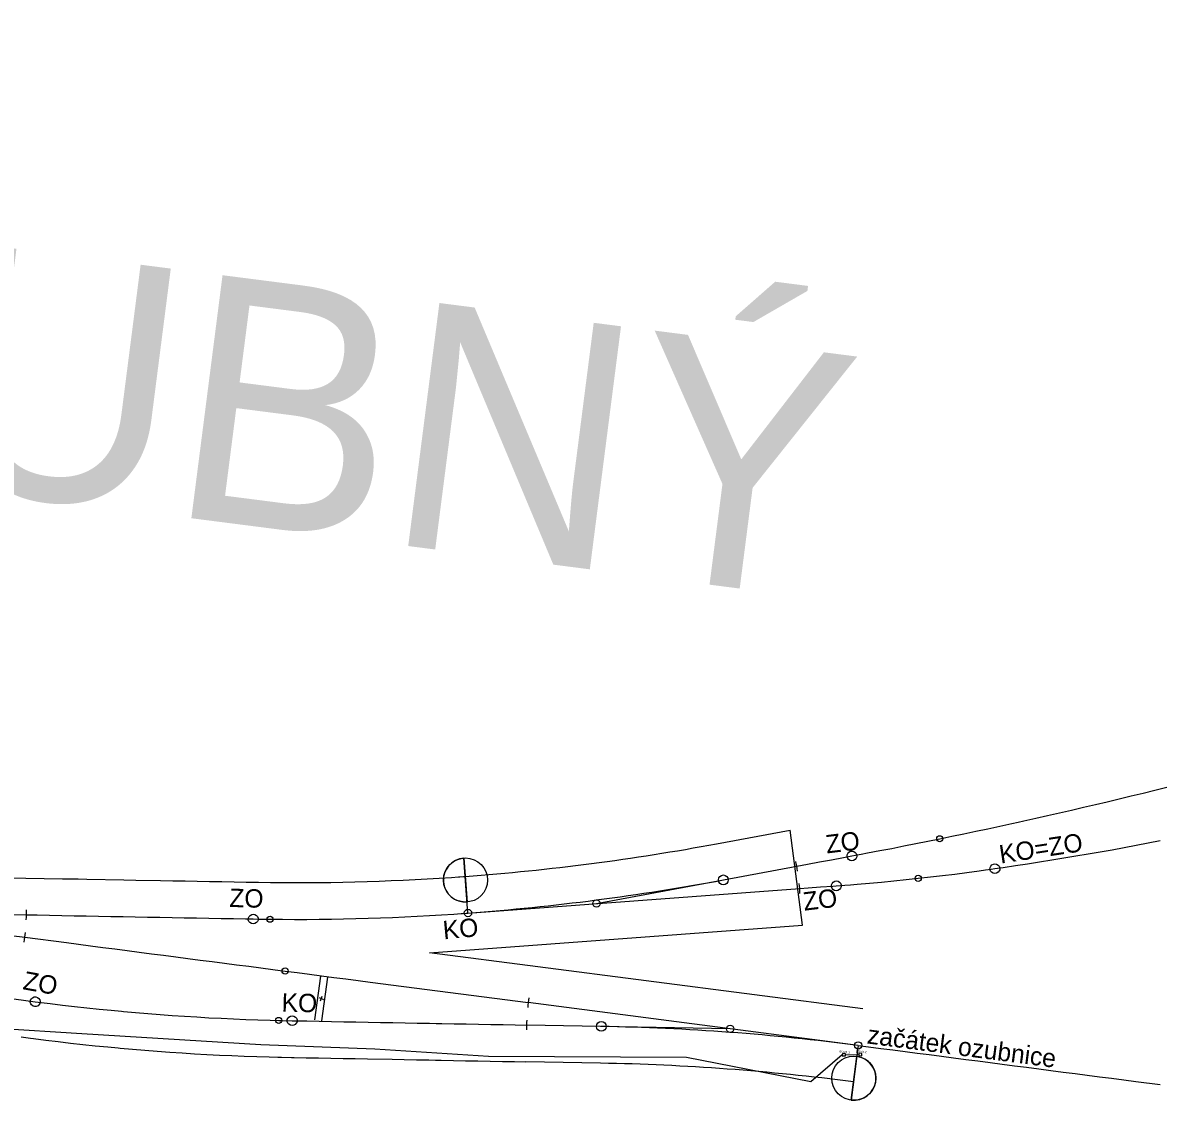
# Model space of a CAD drawing. Extents: x -669661 to -669105, y -977202 to -977030.
# Drawn here: x -669172.695 to -669168.055, y -977098.531 to -977094.133 of the extents above; entities that cross this region are included whole.
import ezdxf

# ---------------------------------------------------------------- set-up
doc = ezdxf.new("R2010")
doc.units = 0
doc.layers.add('KOL_námezníky', color=7, linetype='Continuous')
doc.layers.add('Schéma', color=7, linetype='Continuous')

# ---------------------------------------------------------------- blocks, each defined once
blk = doc.blocks.new('Z3.50')
at = {"layer": 'KOL_námezníky'}
for p, q in [((-27.7, 181.3), (-26.5, -174.8)), ((33.2, -174.7), (31.9, 181.4))]:
    blk.add_line(p, q, dxfattribs=at)

msp = doc.modelspace()

# ---------------------------------------------------------------- linework, layer by layer
at = {"layer": 'Schéma'}
for p, q in [((-669168.1733, -977097.2885), (-669168.1247, -977097.2766)), ((-669168.1247, -977097.2766), (-669168.0762, -977097.2646)), ((-669168.0762, -977097.2646), (-669168.0277, -977097.2524)), ((-669168.3678, -977097.3349), (-669168.3192, -977097.3235)), ((-669168.3192, -977097.3235), (-669168.2705, -977097.3119)), ((-669168.2705, -977097.3119), (-669168.2219, -977097.3002)), ((-669168.2219, -977097.3002), (-669168.1733, -977097.2885)), ((-669168.5628, -977097.3795), (-669168.514, -977097.3685)), ((-669168.514, -977097.3685), (-669168.4653, -977097.3574)), ((-669168.4653, -977097.3574), (-669168.4165, -977097.3462)), ((-669168.4165, -977097.3462), (-669168.3678, -977097.3349)), ((-669168.7582, -977097.4223), (-669168.7093, -977097.4118)), ((-669168.7093, -977097.4118), (-669168.6604, -977097.4011)), ((-669168.6604, -977097.4011), (-669168.6347, -977097.3955)), ((-669168.6347, -977097.3955), (-669168.6116, -977097.3904)), ((-669168.6116, -977097.3904), (-669168.5628, -977097.3795)), ((-669169.8644, -977097.4837), (-669169.5649, -977097.4278)), ((-669169.5145, -977097.816), (-669169.5649, -977097.4278)), ((-669169.0029, -977097.4732), (-669168.9539, -977097.4632)), ((-669168.9539, -977097.4632), (-669168.9049, -977097.4532)), ((-669168.9049, -977097.4532), (-669168.856, -977097.443)), ((-669168.856, -977097.443), (-669168.8071, -977097.4327)), ((-669168.8071, -977097.4327), (-669168.7582, -977097.4223)), ((-669169.2483, -977097.5212), (-669169.1992, -977097.5118)), ((-669169.1992, -977097.5118), (-669169.1501, -977097.5024)), ((-669169.1501, -977097.5024), (-669169.101, -977097.4927)), ((-669169.101, -977097.4927), (-669169.0519, -977097.483)), ((-669169.0519, -977097.483), (-669169.0029, -977097.4732)), ((-669168.3001, -977097.5166), (-669168.2508, -977097.5079)), ((-669168.2508, -977097.5079), (-669168.2016, -977097.4989)), ((-669168.2016, -977097.4989), (-669168.1525, -977097.4898)), ((-669168.1525, -977097.4898), (-669168.1034, -977097.4805)), ((-669168.1034, -977097.4805), (-669168.0543, -977097.471)), ((-669170.8788, -977097.7664), (-669170.8954, -977097.542)), ((-669169.494, -977097.5672), (-669169.4449, -977097.558)), ((-669169.4449, -977097.558), (-669169.3957, -977097.5488)), ((-669169.3957, -977097.5488), (-669169.3465, -977097.5397)), ((-669169.3465, -977097.5397), (-669169.3122, -977097.5332)), ((-669169.3122, -977097.5332), (-669169.2974, -977097.5305)), ((-669169.2974, -977097.5305), (-669169.2742, -977097.5261)), ((-669169.2742, -977097.5261), (-669169.2483, -977097.5212)), ((-669168.5961, -977097.5654), (-669168.5467, -977097.5577)), ((-669168.5467, -977097.5577), (-669168.4973, -977097.5499)), ((-669168.4973, -977097.5499), (-669168.4479, -977097.5418)), ((-669168.4479, -977097.5418), (-669168.3986, -977097.5336)), ((-669168.3986, -977097.5336), (-669168.3493, -977097.5252)), ((-669168.3493, -977097.5252), (-669168.3001, -977097.5166)), ((-669170.3541, -977097.7276), (-669169.5374, -977097.5753)), ((-669169.5374, -977097.5753), (-669169.494, -977097.5672)), ((-669168.8931, -977097.6072), (-669168.8435, -977097.6008)), ((-669168.8435, -977097.6008), (-669168.794, -977097.5942)), ((-669168.794, -977097.5942), (-669168.7673, -977097.5905)), ((-669168.7673, -977097.5905), (-669168.7445, -977097.5873)), ((-669168.7445, -977097.5873), (-669168.7292, -977097.5852)), ((-669168.7292, -977097.5852), (-669168.695, -977097.5802)), ((-669168.695, -977097.5802), (-669168.6455, -977097.5729)), ((-669168.6455, -977097.5729), (-669168.5961, -977097.5654)), ((-669169.3761, -977097.6553), (-669169.3408, -977097.6527)), ((-669169.3408, -977097.6527), (-669169.3178, -977097.6508)), ((-669169.3178, -977097.6508), (-669169.291, -977097.6487)), ((-669169.291, -977097.6487), (-669169.2411, -977097.6444)), ((-669169.2411, -977097.6444), (-669169.1913, -977097.6399)), ((-669169.1913, -977097.6399), (-669169.1416, -977097.6351)), ((-669169.1416, -977097.6351), (-669169.0918, -977097.63)), ((-669169.0918, -977097.63), (-669169.0421, -977097.6247)), ((-669169.0421, -977097.6247), (-669168.9924, -977097.6191)), ((-669168.9924, -977097.6191), (-669168.9428, -977097.6133)), ((-669168.9428, -977097.6133), (-669168.8931, -977097.6072)), ((-669174.0323, -977097.6905), (-669172.6867, -977097.8652)), ((-669170.8788, -977097.7664), (-669169.5256, -977097.6664)), ((-669169.5256, -977097.6664), (-669169.4904, -977097.6638)), ((-669169.4904, -977097.6638), (-669169.4405, -977097.6601)), ((-669169.4405, -977097.6601), (-669169.3907, -977097.6564)), ((-669169.3907, -977097.6564), (-669169.3761, -977097.6553)), ((-669173.5106, -977097.7582), (-669172.6799, -977097.7736)), ((-669172.6799, -977097.7736), (-669172.6358, -977097.7744)), ((-669172.6358, -977097.7744), (-669172.5858, -977097.7753)), ((-669172.5858, -977097.7753), (-669172.5358, -977097.7762)), ((-669172.5358, -977097.7762), (-669172.4858, -977097.7772)), ((-669172.4858, -977097.7772), (-669172.4713, -977097.7774)), ((-669172.4713, -977097.7774), (-669172.4358, -977097.7781)), ((-669172.4358, -977097.7781), (-669172.3858, -977097.779)), ((-669172.3858, -977097.779), (-669172.3358, -977097.7799)), ((-669172.3358, -977097.7799), (-669172.2859, -977097.7809)), ((-669172.2859, -977097.7809), (-669172.2359, -977097.7818)), ((-669172.2359, -977097.7818), (-669172.1859, -977097.7827)), ((-669172.1859, -977097.7827), (-669172.1359, -977097.7836)), ((-669172.1359, -977097.7836), (-669172.0859, -977097.7846)), ((-669172.0859, -977097.7846), (-669172.0359, -977097.7855)), ((-669172.0359, -977097.7855), (-669171.9859, -977097.7864)), ((-669171.9859, -977097.7864), (-669171.9359, -977097.7873)), ((-669171.9359, -977097.7873), (-669171.8859, -977097.7882)), ((-669171.8859, -977097.7882), (-669171.8359, -977097.7892)), ((-669171.8359, -977097.7892), (-669171.7859, -977097.7901)), ((-669171.7859, -977097.7901), (-669171.7547, -977097.7907)), ((-669171.7547, -977097.7907), (-669171.7359, -977097.791)), ((-669171.7359, -977097.791), (-669171.686, -977097.7917)), ((-669171.686, -977097.7917), (-669171.636, -977097.7921)), ((-669171.536, -977097.7922), (-669171.486, -977097.7918)), ((-669171.486, -977097.7918), (-669171.436, -977097.7912)), ((-669171.436, -977097.7912), (-669171.386, -977097.7903)), ((-669171.386, -977097.7903), (-669171.336, -977097.7892)), ((-669171.336, -977097.7892), (-669171.286, -977097.7878)), ((-669171.286, -977097.7878), (-669171.236, -977097.7861)), ((-669171.236, -977097.7861), (-669171.1861, -977097.7842)), ((-669171.1861, -977097.7842), (-669171.1361, -977097.782)), ((-669171.1361, -977097.782), (-669171.0862, -977097.7795)), ((-669171.0862, -977097.7795), (-669171.0362, -977097.7768)), ((-669171.0362, -977097.7768), (-669170.9863, -977097.7738)), ((-669170.9863, -977097.7738), (-669170.9364, -977097.7705)), ((-669170.9364, -977097.7705), (-669170.907, -977097.7685)), ((-669170.907, -977097.7685), (-669170.901, -977097.7681)), ((-669170.901, -977097.7681), (-669170.8866, -977097.767)), ((-669170.8866, -977097.767), (-669170.8788, -977097.7664)), ((-669171.636, -977097.7921), (-669171.586, -977097.7923)), ((-669171.586, -977097.7923), (-669171.536, -977097.7922)), ((-669171.0352, -977097.9284), (-669169.5145, -977097.816)), ((-669172.6867, -977097.8652), (-669172.5172, -977097.8872)), ((-669172.5172, -977097.8872), (-669172.4676, -977097.8937)), ((-669172.4676, -977097.8937), (-669172.418, -977097.9001)), ((-669172.418, -977097.9001), (-669172.3684, -977097.9065)), ((-669172.3684, -977097.9065), (-669172.3188, -977097.913)), ((-669172.3188, -977097.913), (-669172.2692, -977097.9194)), ((-669172.2692, -977097.9194), (-669172.2197, -977097.9259)), ((-669172.2197, -977097.9259), (-669172.1701, -977097.9323)), ((-669169.2679, -977098.1579), (-669171.0352, -977097.9284)), ((-669172.1701, -977097.9323), (-669172.1205, -977097.9387)), ((-669172.1205, -977097.9387), (-669172.0709, -977097.9452)), ((-669172.0709, -977097.9452), (-669172.0213, -977097.9516)), ((-669172.0213, -977097.9516), (-669171.9717, -977097.9581)), ((-669171.9717, -977097.9581), (-669171.9222, -977097.9645)), ((-669171.9222, -977097.9645), (-669171.8726, -977097.9709)), ((-669171.8726, -977097.9709), (-669171.823, -977097.9774)), ((-669171.823, -977097.9774), (-669171.7734, -977097.9838)), ((-669171.7734, -977097.9838), (-669171.7238, -977097.9902)), ((-669171.7238, -977097.9902), (-669171.6742, -977097.9967)), ((-669171.6742, -977097.9967), (-669171.6246, -977098.0031)), ((-669171.6246, -977098.0031), (-669171.5751, -977098.0096)), ((-669171.5751, -977098.0096), (-669171.5255, -977098.016)), ((-669171.5255, -977098.016), (-669171.4759, -977098.0224)), ((-669171.4759, -977098.0224), (-669171.4263, -977098.0289)), ((-669171.4263, -977098.0289), (-669171.3767, -977098.0353)), ((-669171.3767, -977098.0353), (-669171.3271, -977098.0418)), ((-669171.3271, -977098.0418), (-669171.2776, -977098.0482)), ((-669171.2776, -977098.0482), (-669170.6328, -977098.1319)), ((-669171.4864, -977098.1118), (-669171.4678, -977098.1193)), ((-669171.4809, -977098.1249), (-669171.4735, -977098.1062)), ((-669172.7314, -977098.1171), (-669172.6819, -977098.1235)), ((-669172.6819, -977098.1235), (-669172.644, -977098.1284)), ((-669172.644, -977098.1284), (-669172.6323, -977098.1299)), ((-669172.6323, -977098.1299), (-669172.5827, -977098.1362)), ((-669172.5827, -977098.1362), (-669172.533, -977098.1422)), ((-669172.533, -977098.1422), (-669172.4833, -977098.1479)), ((-669172.4833, -977098.1479), (-669172.4336, -977098.1533)), ((-669172.4336, -977098.1533), (-669172.3839, -977098.1585)), ((-669172.3839, -977098.1585), (-669172.3342, -977098.1635)), ((-669169.2872, -977098.3066), (-669170.6328, -977098.1319)), ((-669172.3342, -977098.1635), (-669172.2923, -977098.1674)), ((-669172.2923, -977098.1674), (-669172.2844, -977098.1682)), ((-669172.2844, -977098.1682), (-669172.2346, -977098.1726)), ((-669172.2346, -977098.1726), (-669172.1848, -977098.1767)), ((-669172.1848, -977098.1767), (-669172.1349, -977098.1806)), ((-669172.1349, -977098.1806), (-669172.085, -977098.1842)), ((-669172.085, -977098.1842), (-669172.0351, -977098.1876)), ((-669172.0351, -977098.1876), (-669171.9852, -977098.1907)), ((-669171.9852, -977098.1907), (-669171.9353, -977098.1935)), ((-669171.9353, -977098.1935), (-669171.8854, -977098.1961)), ((-669171.8854, -977098.1961), (-669171.8354, -977098.1984)), ((-669171.8354, -977098.1984), (-669171.7855, -977098.2005)), ((-669171.7855, -977098.2005), (-669171.7355, -977098.2023)), ((-669171.7355, -977098.2023), (-669171.6855, -977098.2038)), ((-669171.6855, -977098.2038), (-669171.651, -977098.2047)), ((-669171.651, -977098.2047), (-669171.6356, -977098.2051)), ((-669171.6356, -977098.2051), (-669171.5961, -977098.2059)), ((-669171.5961, -977098.2059), (-669171.5856, -977098.2061)), ((-669171.5856, -977098.2061), (-669171.5356, -977098.207)), ((-669171.5356, -977098.207), (-669171.4856, -977098.2079)), ((-669171.4856, -977098.2079), (-669171.4356, -977098.2088)), ((-669171.4356, -977098.2088), (-669171.3856, -977098.2098)), ((-669172.4538, -977098.259), (-669172.8186, -977098.2366)), ((-669171.3856, -977098.2098), (-669171.3356, -977098.2107)), ((-669171.3356, -977098.2107), (-669171.2856, -977098.2116)), ((-669171.2856, -977098.2116), (-669171.2356, -977098.2125)), ((-669171.2356, -977098.2125), (-669171.1856, -977098.2135)), ((-669171.1856, -977098.2135), (-669171.1356, -977098.2144)), ((-669171.1356, -977098.2144), (-669171.0857, -977098.2153)), ((-669171.0857, -977098.2153), (-669171.0357, -977098.2162)), ((-669171.0357, -977098.2162), (-669171.0086, -977098.2167)), ((-669171.0086, -977098.2167), (-669170.9857, -977098.2172)), ((-669170.9857, -977098.2172), (-669170.9357, -977098.2181)), ((-669170.9357, -977098.2181), (-669170.8857, -977098.219)), ((-669170.8857, -977098.219), (-669170.8357, -977098.2199)), ((-669170.8357, -977098.2199), (-669170.7857, -977098.2208)), ((-669170.7857, -977098.2208), (-669170.7357, -977098.2218)), ((-669170.7357, -977098.2218), (-669170.6857, -977098.2227)), ((-669170.6857, -977098.2227), (-669170.6396, -977098.2235)), ((-669169.809, -977098.2389), (-669170.6396, -977098.2235)), ((-669171.7241, -977098.3042), (-669172.4538, -977098.259)), ((-669171.259, -977098.3225), (-669171.7241, -977098.3042)), ((-669170.7944, -977098.3526), (-669171.259, -977098.3225)), ((-669169.3525, -977098.3452), (-669169.4804, -977098.4556)), ((-669169.3513, -977098.3398), (-669169.3518, -977098.3489)), ((-669169.3518, -977098.3489), (-669169.3393, -977098.3495)), ((-669169.3388, -977098.3404), (-669169.3513, -977098.3398)), ((-669169.3393, -977098.3495), (-669169.3388, -977098.3404)), ((-669169.339, -977098.345), (-669169.2844, -977098.3434)), ((-669169.2872, -977098.3066), (-669169.3161, -977098.5298)), ((-669169.2842, -977098.3388), (-669169.2846, -977098.348)), ((-669169.2846, -977098.348), (-669169.2721, -977098.3486)), ((-669169.2716, -977098.3395), (-669169.2842, -977098.3388)), ((-669169.2721, -977098.3486), (-669169.2716, -977098.3395)), ((-669169.9874, -977098.3559), (-669170.7944, -977098.3526)), ((-669170.3378, -977098.3791), (-669170.6423, -977098.3735)), ((-669169.4804, -977098.4556), (-669169.9874, -977098.3559))]:
    msp.add_line(p, q, dxfattribs=at)
for points in [[(-669169.3126, -977097.5532), (-669169.3192, -977097.5518), (-669169.3258, -977097.5477), (-669169.3297, -977097.5436), (-669169.3323, -977097.5369), (-669169.3321, -977097.5289), (-669169.3294, -977097.5236), (-669169.3253, -977097.5183), (-669169.3185, -977097.5145), (-669169.3118, -977097.5133), (-669169.3052, -977097.5147), (-669169.2986, -977097.5188), (-669169.2947, -977097.5229), (-669169.2921, -977097.5296), (-669169.2923, -977097.5376), (-669169.295, -977097.5429), (-669169.2991, -977097.5482), (-669169.3059, -977097.552), (-669169.3126, -977097.5532)], [(-669170.8954, -977097.542), (-669170.8821, -977097.7216), (-669170.8821, -977097.7216)], [(-669168.7295, -977097.6052), (-669168.7362, -977097.6037), (-669168.7428, -977097.5996), (-669168.7467, -977097.5955), (-669168.7492, -977097.5888), (-669168.7491, -977097.5808), (-669168.7463, -977097.5755), (-669168.7422, -977097.5702), (-669168.7355, -977097.5664), (-669168.7288, -977097.5652), (-669168.7222, -977097.5666), (-669168.7156, -977097.5707), (-669168.7116, -977097.5748), (-669168.7091, -977097.5815), (-669168.7092, -977097.5895), (-669168.712, -977097.5948), (-669168.7161, -977097.6001), (-669168.7228, -977097.6039), (-669168.7295, -977097.6052)], [(-669172.9817, -977097.618), (-669172.533, -977097.6263), (-669172.483, -977097.6272), (-669172.4686, -977097.6275), (-669172.4331, -977097.6281), (-669172.2831, -977097.6309), (-669172.2331, -977097.6318), (-669172.1331, -977097.6337), (-669172.0831, -977097.6346), (-669172.0331, -977097.6355), (-669171.9831, -977097.6364), (-669171.9331, -977097.6374), (-669171.8832, -977097.6383), (-669171.8332, -977097.6392), (-669171.7832, -977097.6401), (-669171.752, -977097.6407), (-669171.7336, -977097.641), (-669171.6843, -977097.6417), (-669171.6351, -977097.6421), (-669171.5858, -977097.6423), (-669171.5366, -977097.6422), (-669171.4874, -977097.6418), (-669171.4382, -977097.6412), (-669171.389, -977097.6404), (-669171.3398, -977097.6392), (-669171.2906, -977097.6378), (-669171.2414, -977097.6362), (-669171.1923, -977097.6343), (-669171.1431, -977097.6321), (-669171.094, -977097.6297), (-669171.0448, -977097.627), (-669170.9957, -977097.6241), (-669170.9465, -977097.6209), (-669170.9176, -977097.6188), (-669170.9118, -977097.6184), (-669170.8975, -977097.6174), (-669170.8898, -977097.6168)], [(-669169.3765, -977097.6753), (-669169.3831, -977097.6739), (-669169.3897, -977097.6698), (-669169.3937, -977097.6657), (-669169.3962, -977097.659), (-669169.3961, -977097.651), (-669169.3933, -977097.6457), (-669169.3892, -977097.6404), (-669169.3825, -977097.6366), (-669169.3758, -977097.6353), (-669169.3691, -977097.6368), (-669169.3625, -977097.6409), (-669169.3586, -977097.645), (-669169.3561, -977097.6517), (-669169.3562, -977097.6597), (-669169.359, -977097.665), (-669169.3631, -977097.6702), (-669169.3698, -977097.6741), (-669169.3765, -977097.6753)], [(-669171.755, -977097.8107), (-669171.7617, -977097.8092), (-669171.7683, -977097.8051), (-669171.7722, -977097.801), (-669171.7748, -977097.7943), (-669171.7746, -977097.7863), (-669171.7718, -977097.781), (-669171.7677, -977097.7758), (-669171.761, -977097.7719), (-669171.7543, -977097.7707), (-669171.7477, -977097.7721), (-669171.7411, -977097.7763), (-669171.7372, -977097.7803), (-669171.7346, -977097.787), (-669171.7348, -977097.795), (-669171.7375, -977097.8003), (-669171.7416, -977097.8056), (-669171.7484, -977097.8095), (-669171.755, -977097.8107)], [(-669172.6466, -977098.1482), (-669172.653, -977098.1461), (-669172.6591, -977098.1412), (-669172.6625, -977098.1368), (-669172.6643, -977098.1298), (-669172.6633, -977098.1219), (-669172.66, -977098.1169), (-669172.6553, -977098.1121), (-669172.6482, -977098.109), (-669172.6414, -977098.1086), (-669172.635, -977098.1108), (-669172.6289, -977098.1156), (-669172.6254, -977098.1201), (-669172.6236, -977098.127), (-669172.6247, -977098.135), (-669172.628, -977098.1399), (-669172.6327, -977098.1447), (-669172.6398, -977098.1478), (-669172.6466, -977098.1482)], [(-669171.5965, -977098.2259), (-669171.6031, -977098.2244), (-669171.6097, -977098.2203), (-669171.6137, -977098.2162), (-669171.6162, -977098.2095), (-669171.6161, -977098.2015), (-669171.6133, -977098.1962), (-669171.6092, -977098.191), (-669171.6025, -977098.1871), (-669171.5958, -977098.1859), (-669171.5891, -977098.1873), (-669171.5825, -977098.1915), (-669171.5786, -977098.1955), (-669171.5761, -977098.2022), (-669171.5762, -977098.2102), (-669171.579, -977098.2155), (-669171.5831, -977098.2208), (-669171.5898, -977098.2247), (-669171.5965, -977098.2259)], [(-669172.7012, -977098.2722), (-669172.6633, -977098.2772), (-669172.6512, -977098.2787), (-669172.601, -977098.285), (-669172.5506, -977098.2911), (-669172.5001, -977098.2969), (-669172.4496, -977098.3025), (-669172.3991, -977098.3078), (-669172.3486, -977098.3128), (-669172.3062, -977098.3168), (-669172.2979, -977098.3176), (-669172.2474, -977098.322), (-669172.1968, -977098.3262), (-669172.1462, -977098.3302), (-669172.0955, -977098.3339), (-669172.0448, -977098.3373), (-669171.9942, -977098.3404), (-669171.9435, -977098.3433), (-669171.8927, -977098.3459), (-669171.842, -977098.3483), (-669171.7912, -977098.3504), (-669171.7405, -977098.3522), (-669171.6898, -977098.3537), (-669171.6547, -977098.3547), (-669171.6389, -977098.355), (-669171.5991, -977098.3558), (-669171.5883, -977098.356), (-669171.5383, -977098.357), (-669171.4884, -977098.3579), (-669171.4384, -977098.3588), (-669171.3884, -977098.3597), (-669171.3384, -977098.3607), (-669171.2884, -977098.3616), (-669171.1884, -977098.3634), (-669171.1384, -977098.3644), (-669171.0884, -977098.3653), (-669171.0384, -977098.3662), (-669171.0113, -977098.3667), (-669170.9884, -977098.3671), (-669170.9384, -977098.368), (-669170.8885, -977098.369), (-669170.8385, -977098.3699), (-669170.7385, -977098.3717), (-669170.6885, -977098.3727), (-669170.6423, -977098.3735)], [(-669169.2872, -977098.3066), (-669169.2446, -977098.3122), (-669169.195, -977098.3186), (-669169.1455, -977098.325), (-669169.0959, -977098.3315), (-669169.0463, -977098.3379), (-669168.9967, -977098.3444), (-669168.9471, -977098.3508), (-669168.8975, -977098.3572), (-669168.848, -977098.3637), (-669168.7984, -977098.3701), (-669168.7488, -977098.3765), (-669168.6992, -977098.383), (-669168.6496, -977098.3894), (-669168.6, -977098.3959), (-669168.5505, -977098.4023), (-669168.5009, -977098.4087), (-669168.4513, -977098.4152), (-669168.4017, -977098.4216), (-669168.3521, -977098.428), (-669168.3025, -977098.4345), (-669168.253, -977098.4409), (-669168.2034, -977098.4474), (-669168.1538, -977098.4538), (-669168.0546, -977098.4667)], [(-669169.3161, -977098.5298), (-669169.293, -977098.3513), (-669169.293, -977098.3513)]]:
    msp.add_lwpolyline(points, dxfattribs=at)
for centre, radius in [((-669168.9541, -977097.4633), 0.0125), ((-669170.8888, -977097.6318), 0.09), ((-669169.8368, -977097.6311), 0.02), ((-669169.0421, -977097.6247), 0.0125), ((-669170.3541, -977097.7276), 0.015), ((-669171.686, -977097.7917), 0.0125), ((-669170.8788, -977097.7664), 0.015), ((-669171.6246, -977098.0031), 0.0125), ((-669171.651, -977098.2047), 0.0125), ((-669170.335, -977098.2292), 0.02), ((-669169.809, -977098.2389), 0.015), ((-669169.2872, -977098.3066), 0.015), ((-669169.3046, -977098.4405), 0.09)]:
    msp.add_circle(centre, radius, dxfattribs=at)
for centre, radius, start, end in [((-669171.5793, -977088.2923), 9.35, 274.22836, 280.56855), ((-669170.8888, -977097.6318), 0.09, 94.2284, 274.2269), ((-669170.3541, -977097.7276), 0.8308, 9.1892, 11.9479), ((-669171.5793, -977088.2923), 9.5, 274.22836, 280.56839), ((-669170.3541, -977097.7276), 0.8308, 2.849, 5.6077), ((-669173.5106, -977097.7582), 0.8308, 357.5628, 0.3215), ((-669173.5106, -977097.7582), 0.8308, 351.2226, 353.9813), ((-669169.8089, -977098.2389), 0.8308, 171.2226, 173.9813), ((-669169.8089, -977098.2389), 0.8308, 177.5628, 180.3215), ((-669170.5104, -977107.7276), 9.5, 82.60197, 88.942), ((-669170.5104, -977107.7276), 9.35, 82.60197, 88.942), ((-669169.3046, -977098.4405), 0.09, 262.602, 82.6005)]:
    msp.add_arc(centre, radius, start, end, dxfattribs=at)

# ---------------------------------------------------------------- block references
at = {"layer": 'Schéma', "xscale": 0.0005052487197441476, "yscale": 0.0005052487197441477, "rotation": -8.02863514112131}
msp.add_blockref('Z3.50', (-669171.4787, -977098.1168), dxfattribs=at)

# ---------------------------------------------------------------- texts
at = {"layer": 'Schéma'}
for s, height, rotation, p in [('DOLNÍ POLUBNÝ', 1, 352.6919, (-669180.15, -977095.1109)), ('ZO', 0.075, 6.9962, (-669169.4149, -977097.5235)), ('KO=ZO', 0.075, 8.6069, (-669168.7056, -977097.5648)), ('ZO', 0.075, 358.441, (-669171.853, -977097.7415)), ('ZO', 0.075, 6.9962, (-669169.5068, -977097.7571)), ('KO', 0.075, 5.3287, (-669170.9778, -977097.8741)), ('ZO', 0.075, 349.8595, (-669172.6977, -977098.0771)), ('KO', 0.075, 358.5059, (-669171.6397, -977098.1682)), ('začátek ozubnice', 0.075, 352.6118, (-669169.2533, -977098.2983)), ('EOV4.1', 0.009, 357.0527, (-669169.3641, -977098.3371)), ('EOV4.2', 0.009, 357.0527, (-669169.2969, -977098.3362))]:
    msp.add_text(s, height=height, rotation=rotation, dxfattribs=at).set_placement(p)

doc.saveas('drawing.dxf')
